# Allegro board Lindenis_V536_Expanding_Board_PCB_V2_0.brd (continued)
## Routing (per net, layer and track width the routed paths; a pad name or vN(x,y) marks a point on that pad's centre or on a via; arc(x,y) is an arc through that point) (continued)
SDC0-CLK: length 26.1
  TOP w0.102: v1(91.69,15.62) 90.97,14.9 77.05,14.9 74.17,17.78 73.08,17.78 72.77,18.08 U901.100
  BOTTOM w0.102: J3.5 89.15,14.34 89.53,14.73 90.17,14.73 91.65,16.21 D11.1 v1(91.69,15.62)
SDC0-CMD: length 19.8
  TOP w0.102: v1(88.14,15.62) 87.72,15.2 77.25,15.2 74.04,18.41 U901.101
  BOTTOM w0.102: J3.3 86.94,15.02 D12.1 v1(88.14,15.62)
SDC0-D0: length 27.5
  TOP w0.102: U901.99 71.5,18.16 71.75,17.91 72.47,17.91 72.9,17.48 74.04,17.48 76.92,14.59 91.56,14.59 v1(92.58,15.62)
  BOTTOM w0.102: v1(92.58,15.62) D15.1 92.2,15.83 92.2,15.37 91.35,14.51 J3.7
SDC0-D1: length 29.8
  TOP w0.102: v1(93.47,15.62) 92.24,14.39 76.79,14.39 73.91,17.27 72.81,17.27 72.43,17.65 70.61,17.65 70.23,18.03 U901.98
  BOTTOM w0.102: J3.8 92.45,14.09 93.03,14.67 93.03,15.77 D16.1 v1(93.47,15.62)
SDC0-D2: length 14.1
  TOP w0.102: v1(84.71,15.88) 77.85,15.88 76.58,17.14 U901.103
  BOTTOM w0.102: J3.1 84.75,14.26 85.34,14.86 D14.1 85.05,16.21 v1(84.71,15.88)
SDC0-D3: length 18
  TOP w0.102: U901.102 75.31,17.78 77.57,15.52 84.86,15.52 85.02,15.69 v1(86.74,15.69)
  BOTTOM w0.102: v1(86.74,15.69) 87.25,16.19 RC9.1 D13.1 85.84,15.57 J3.2
SDC0-DET: length 19.6
  TOP w0.102: v1(93.85,17.65) 92.71,16.51 78.16,16.51 77.85,16.81 U901.104
  BOTTOM w0.102: v1(93.85,17.65) 94.36,17.14 R401.2
TS: length 62.2
  TOP w0.102: U901.29 58.8,69.85 v1(58.67,69.98) ; v1(44.58,71.58) 43.99,71.58 42.29,73.28 v1(40.13,73.28)
  BOTTOM w0.102: v1(44.58,71.58) 44.7,71.7 44.7,73.18 44.81,73.28 48.64,73.28 50.24,71.68 54.18,71.68 54.48,71.37 54.48,69.98 54.74,69.72 58.42,69.72 v1(58.67,69.98) ; v1(40.13,73.28) 40,73.41 27.05,73.41 26.21,72.57 20.78,72.57 18.03,75.31 12.45,75.31 9.78,72.64 7.11,72.64 5.84,73.91 J1.2
TWI1-SCK: length 108.4
  TOP w0.102: v1(51.69,81.41) 53.34,79.76 78.52,79.76 78.82,80.06 80.6,80.06 v1(80.84,79.82) ; v1(123.83,65.41) 123.74,65.41 R531.1 122.83,64.49 121.64,64.49 120.65,63.5 120.65,60.58 119.53,59.46 111.91,59.46 110.49,58.04 98.78,58.04 97.03,59.79 97.03,70.23 96.65,70.61 84.63,70.61 v1(84.25,70.23) 88.39,70.23 89.28,69.34 U901.5 ; JL6.6 124.95,65.64 v1(124.84,65.53)
  BOTTOM w0.102: R41.2 80.69,79.97 v1(80.84,79.82) 80.84,79.81 80.14,79.11 80.14,77.72 U11.2 81.28,76.58 81.28,74.58 83.72,72.14 83.72,70.76 v1(84.25,70.23) ; v1(124.84,65.53) 123.95,65.53 v1(123.83,65.41) ; R75.1 52.32,80.77 v1(51.69,81.41) 51.69,82.04 J36.3
TWI1-SDA: length 109.8
  TOP w0.102: v1(79.71,79.71) 79.71,79.71 79.48,79.48 53.12,79.48 51.19,81.41 v1(50.8,81.41) ; JL6.5 124.6,65.14 123.95,65.79 R532.1 122.83,65.38 121.64,65.38 120.45,64.19 120.45,60.66 119.45,59.66 111.83,59.66 110.41,58.24 98.86,58.24 97.28,59.82 97.28,70.26 96.73,70.82 84.1,70.82 83.82,70.54 v1(83.82,69.95) 83.9,69.88 84.4,69.88 84.55,70.03 87.71,70.03 88.01,69.72 U901.6
  BOTTOM w0.102: R40.2 79.55,79.97 79.71,79.8 v1(79.71,79.71) 79.71,78.69 79.25,78.23 79.25,76.07 U11.1 81.15,74.17 81.41,74.17 83.52,72.06 83.52,70.26 v1(83.82,69.95) ; J36.4 50.8,81.66 v1(50.8,81.41) 51.43,80.77 R76.1
TXC: length 54.3
  TOP w0.102: v1(28.5,59.74) 28.42,59.82 27.97,59.82 26.8,60.98 UM1.20
  BOTTOM w0.102: v1(28.5,59.74) 28.55,59.79 28.55,60.73 30.94,63.12 38.48,63.12 40.51,65.15 42.85,65.15 43.61,65.91 71.75,65.91 74.04,68.2 74.04,68.88 CM11.1 RM12.1
TXCTL: length 42.7
  TOP w0.102: UM1.19 v1(26.4,60.45)
  BOTTOM w0.102: v1(26.4,60.45) 26.4,61.07 30.28,64.95 37.57,64.95 39.51,66.89 42.18,66.89 43.33,68.05 64.28,68.05 RM54.1
TXD0: length 48.1
  TOP w0.102: UM1.18 26,60.08 v1(26.42,59.67)
  BOTTOM w0.102: v1(26.42,59.67) 26.74,59.67 27,59.93 27,61.09 30.42,64.52 37.72,64.52 39.67,66.47 42.33,66.47 43.45,67.59 68.48,67.59 68.82,67.93 RM5.8
TXD1: length 49.9
  TOP w0.102: v1(25.65,59.67) 25.6,59.72 UM1.17
  BOTTOM w0.102: RM5.7 69.47,67.57 69.27,67.36 43.51,67.36 42.42,66.27 39.76,66.27 37.8,64.31 30.51,64.31 27.2,61.01 27.2,59.84 26.67,59.31 26.01,59.31 v1(25.65,59.67)
TXD2: length 51.1
  TOP w0.102: v1(25.15,59.67) 25.2,59.73 UM1.16
  BOTTOM w0.102: v1(25.15,59.67) 25.71,59.11 26.75,59.11 27.41,59.76 27.41,60.93 30.59,64.11 37.89,64.11 39.84,66.07 42.5,66.07 43.57,67.13 69.55,67.13 69.97,67.56 RM5.6
TXD3: length 52.4
  TOP w0.102: UM1.15 24.8,59.83 24.79,59.82 24.79,59.52 25.14,59.17 v1(25.14,59.16)
  BOTTOM w0.102: RM5.5 70.62,67.45 70.08,66.9 43.63,66.9 42.59,65.86 39.93,65.86 37.97,63.91 30.68,63.91 27.61,60.84 27.61,59.67 26.84,58.9 25.43,58.9 25.17,59.16 v1(25.14,59.16)
UART4_RX: length 24
  TOP w0.102: v1(96.09,69.62) 95.4,70.31 91.26,70.31 90.55,69.6 U901.4 ; Q2.2 103.06,73.68 R13.1 103.5,72.18 103.5,68.71 103.21,68.41 RG1.1 RG4.1 103.59,67.35 v1(103.63,67.31)
  BOTTOM w0.102: v1(96.09,69.62) 99.92,69.62 102.23,67.31 v1(103.63,67.31)
UART4_TX: length 21
  TOP w0.102: v1(95.58,69.62) 95.17,70.03 92.13,70.03 91.82,69.72 U901.3 ; R348.2 99.69,74.93 101.09,73.53 101.09,72.64 101.68,72.06 101.68,68.76 102.02,68.41 RG2.1 RG5.1 v1(101.52,67.35)
  BOTTOM w0.102: v1(95.58,69.62) 95.59,69.62 95.99,69.22 99.66,69.22 v1(101.52,67.35)
USB1-DM: length 16.9
  TOP w0.114: U51.4 33.42,47.12 33.51,47.22 33.89,47.22 43.79,57.12 44.31,57.12 44.42,57.01 44.42,56.76 44.54,56.64 U901.49
USB1-DP: length 16.9
  TOP w0.114: U901.48 44.54,57.91 44.42,57.8 44.42,57.54 44.31,57.43 43.66,57.43 33.76,47.53 33.51,47.53 33.42,47.62 U51.3
USB1_DM: length 11.2
  TOP w0.114: U32.25 36.42,42.11 36.25,42.29 35.77,42.29 35.33,42.72 35.33,44.5 35.92,45.09 38.18,45.09 38.84,45.74 38.84,47.14 38.26,47.72 37.71,47.72 37.62,47.62 U51.8
USB1_DP: length 11.2
  TOP w0.114: U32.26 36.42,42.76 36.25,42.59 35.89,42.59 35.64,42.85 35.64,44.37 36.04,44.78 38.3,44.78 39.14,45.62 39.14,47.27 38.38,48.03 37.71,48.03 37.62,48.13 U51.9
USB-SEL: length 2.3
  TOP w0.102: R419.1 31.91,48.13 U51.2
USB_RESET: length 4.7
  TOP w0.102: C218.2 R229.1 R238.2 28.31,36.26 U32.13
USBVBUS: length 98.8
  TOP w0.406: v1(92.7,47.24) 92.46,47.24 v1(86.87,52.83) ; v1(51.41,59.82) 51.41,52.93 v1(50.8,52.32)
  TOP w0.508: 9.56,40.71 J9.8 ; J9.8 10.44,39.83 ; J9.8 11.32,40.71 ; J9.4 14.03,40.71 ; J9.4 13.15,41.59 ; J9.4 12.27,40.71 ; J9.4 13.15,39.83
  BOTTOM w0.406: v2(19.43,43.18) 27.18,50.93 38.61,50.93 47.5,59.82 v1(51.41,59.82) ; v1(50.8,52.32) 50.83,52.3 86.33,52.3 v1(86.87,52.83) ; U27.11 v1(92.7,47.24)
  vias: v2(19.43,42.42) v2(19.56,29.21) v2(20.32,29.21)
USIM_CLK: length 61.9
  BOTTOM w0.102: RL25.1 CL29.1 111.3,17.23 110.49,18.03 108.46,18.03 105.79,20.7 105.79,27.69 104.01,29.46 92.52,29.46 87.12,34.86 87.12,51.05 91.3,55.24 U27.19
USIM_DATA: length 65.1
  TOP w0.102: v1(105.41,25.91) v1(106.81,25.91)
  BOTTOM w0.102: U27.17 90.07,53.24 87.88,51.05 87.88,35.18 92.84,30.23 104.65,30.23 106.81,28.07 v1(106.81,25.91) ; RL40.2 112.18,15.11 CW30.1 110.89,15.6 109.88,15.6 109.75,15.73 107.46,15.73 106.81,16.38 106.81,19.3 105.59,20.52 105.59,25.73 v1(105.41,25.91)
USIM_RST: length 57.8
  BOTTOM w0.102: RL24.1 CL28.1 111.3,20.91 110.36,21.84 107.06,21.84 106.3,22.61 106.3,27.94 104.27,29.97 92.73,29.97 87.63,35.07 87.63,51.18 90.69,54.24 U27.18
USIM_VDD: length 78.4
  TOP w0.254: v1(112.35,25.06) v1(104.48,25.06)
  TOP w0.406: v1(104.9,20.19) 107.44,20.19 v1(107.57,20.07)
  BOTTOM w0.254: RL41.1 v1(112.35,25.06)
  BOTTOM w0.305: TP83.1 109.09,18.41 112.58,18.41 112.86,18.69 112.86,18.7 CL31.1
  BOTTOM w0.406: v1(107.57,20.07) 108.71,18.92 TP83.1 ; v1(104.9,20.19) 104.9,24.64 v1(104.48,25.06) 104.48,27.61 103.26,28.83 92.26,28.83 86.49,34.6 86.49,51.18 91.54,56.24 U27.20 ; JL26.C6 113.84,18.41 CL31.1 CL32.1
V-BAT:
  vias: v2(116.84,26.29) v2(117.6,26.29) v2(118.36,26.29) v2(119.13,26.29)
VLED+: length 25.5
  TOP w0.305: J7.35 122.93,50.56 v2(122.68,50.8) 122.94,51.06 J7.36 125.29,51.06 v1(125.95,50.39)
  TOP w0.508: v2(117.22,54.99) 117.28,54.94 D41.2 ; v2(111.44,56.71) C295.2 111.44,54.63 C293.2 U39.5
  BOTTOM w0.305: TP67.1 v1(125.95,50.39)
  BOTTOM w0.508: v2(111.44,56.71) 115.5,56.71 v2(117.22,54.99) 121.41,50.8 v2(122.68,50.8)
VLED-: length 17.3
  TOP w0.305: J7.28 123.08,47.06 v2(122.58,47.56) J7.29 125.66,47.56 v1(125.86,47.75)
  BOTTOM w0.305: v1(125.86,47.75) 126.49,47.12 TP64.1
  BOTTOM w0.508: v2(115.06,55.88) 122.58,48.36 v2(122.58,47.56)
WL-PMU-EN: length 93
  TOP w0.102: v1(87.6,60.91) 87.82,61.13 v1(87.82,66.45) 87.92,66.55 93.73,66.55 94.74,65.53 U901.154
  BOTTOM w0.102: v1(87.82,66.45) 87.63,66.64 R527.2 ; U12.9 34.67,30 34.67,31.62 37.26,34.21 37.26,44.03 49.01,55.78 78.64,55.78 80.01,57.15 82.26,57.15 85.87,60.76 87.45,60.76 v1(87.6,60.91)
WL-SDIO-CLK: length 90.8
  TOP w0.102: v1(93.09,63.55) 92.96,63.42 92.96,61.98 94.49,60.45 U901.150
  BOTTOM w0.102: v1(93.09,63.55) 93.07,63.58 85.55,63.58 81.55,59.58 78.51,59.58 77.24,58.32 48.15,58.32 34.66,44.83 34.66,35.37 31.67,32.38 29.34,32.38 28.58,31.62 28.58,30.1 27.64,29.16 U12.3
WL-SDIO-CMD: length 84.4
  TOP w0.102: v1(93.85,62.48) 94.61,61.72 U901.151
  BOTTOM w0.102: U12.7 32.64,29.96 32.64,31.58 35.69,34.63 35.69,44.33 48.56,57.2 78.03,57.2 79.27,58.45 82.07,58.45 86.06,62.43 93.8,62.43 v1(93.85,62.48)
WL-SDIO-D0: length 93.1
  TOP w0.102: U901.149 94.49,59.18 92.35,61.32 v1(92.35,64.39)
  BOTTOM w0.102: U12.2 28.08,33.4 31.39,33.4 33.69,35.7 33.69,45.13 47.79,59.23 76.98,59.23 78.27,60.53 81.39,60.53 85.45,64.59 91.59,64.59 91.69,64.69 92.05,64.69 v1(92.35,64.39)
WL-SDIO-D1: length 92.3
  TOP w0.102: U901.148 94.36,57.91 91.85,60.43 91.85,64.33 v1(91.84,64.34)
  BOTTOM w0.102: U12.4 27.64,31.58 29.21,33.15 31.5,33.15 33.94,35.6 33.94,45.09 47.88,59.03 77.06,59.03 78.36,60.33 81.47,60.33 85.49,64.34 v1(91.84,64.34)
WL-SDIO-D2: length 85.2
  TOP w0.102: U901.153 94.36,64.26 v1(93.85,63.75)
  BOTTOM w0.102: v1(93.85,63.75) 93.85,63.49 93.2,62.84 85.89,62.84 81.9,58.85 79.1,58.85 77.86,57.61 48.3,57.61 35.27,44.57 35.27,44.41 35.27,34.88 32.18,31.79 30.47,31.79 U12.6
WL-SDIO-D3: length 82.5
  TOP w0.102: U901.152 v1(93.85,62.99)
  BOTTOM w0.102: v1(93.85,62.99) 93.5,62.64 85.97,62.64 81.99,58.65 79.19,58.65 77.94,57.4 48.38,57.4 35.47,44.49 35.47,34.79 U12.8
WL-WAKE-AP: length 127
  TOP w0.102: v1(89.15,60.58) 89.15,60.27 84.94,56.05 84.94,53.04 89.66,48.32 89.66,43.43 89.56,43.33 89.56,43.03 89.66,42.93 89.66,23.82 86.67,20.83 80.77,20.83 80.39,20.45 U901.106
  BOTTOM w0.102: U12.11 36.45,29.77 36.45,33.11 37.46,34.13 37.46,43.94 49.1,55.58 78.72,55.58 80.09,56.95 82.35,56.95 85.95,60.55 89.13,60.55 v1(89.15,60.58)
X1: length 8.1
  TOP w0.102: U32.6 29.29,40.81 27.56,42.55 27.56,42.88 C338.1 26.97,43.05 24.86,43.05 Y3.1
X32KFOUT: length 83.7
  TOP w0.102: v1(91.19,61.72) 91.19,59.82 94.36,56.64 U901.147
  BOTTOM w0.102: v1(91.19,61.72) 91.18,61.72 86.1,61.72 82.12,57.73 79.71,57.73 78.46,56.49 48.61,56.49 36.45,44.34 36.45,34.55 33.64,31.73 U12.10
XI2: length 5.6
  TOP w0.102: Y3.3 26.38,42.21 C230.2 29.22,40.16 U32.7
XTAL-IN: length 7.5
  TOP w0.102: X3.1 25.02,71.5 25.02,69.75 C139.2 24.89,68.95 24.89,68.11 24.8,68.02 UM1.36
XTAL-OUT: length 47.3
  TOP w0.102: R51.2 24.16,67.82 v1(24.38,67.82) 24.51,67.69 24.51,66.41 24.4,66.3 UM1.37
  BOTTOM w0.102: RM56.1 65.15,72.06 64.69,72.52 62.86,72.52 62.48,72.14 62.48,71.25 60.2,68.96 42.95,68.96 41.66,67.67 27.41,67.67 27.05,67.31 24.89,67.31 v1(24.38,67.82)
N17770502: length 1.9
  BOTTOM w0.381: RL23.2 127.51,64.21 CW27.1 127.51,63.16 RL20.1
N17770537: length 6.6
  BOTTOM w0.381: U27.82 126.42,57.24 arc(127.17,57.55) 127.49,58.31 CW26.1 127.49,61.41 RL20.2
N17770634: length 7.6
  BOTTOM w0.381: RL23.1 127.51,71.12 arc(127.42,71.59) 127.15,71.98 v1(126.75,72.39)
N17772040: length 10.2
  BOTTOM w0.102: JL26.C7 115.19,15.88 114.53,16.53 113.01,16.53 112.49,16 DL51.2 112.35,15.96 RL40.1 112.69,14.61 109.09,14.61 TP84.1
N17772586: length 8
  BOTTOM w0.102: TP79.1 111,23.11 111.89,22.23 112.69,22.23 RL41.2 113.71,22.23 JL26.C1
N17773525: length 3.1
  TOP w0.254: UL9.4 103,39.16 CL94.1 RL38.1
N17773548: length 4.4
  TOP w0.254: RL84.2 CL64.2 102.7,41.32 103.09,40.92 UL9.3 103.84,40.94 RL39.2
N17773558: length 17.6
  TOP w0.254: CL64.1 RL84.1 100.63,40.47 100.33,40.77 100.33,42.04 101.22,42.93 107.06,42.93 110.85,39.14 LP7.2
N17773576: length 5.9
  TOP w0.254: CL88.2 106.6,40.85 107.57,39.88 107.57,37.36 LP7.1
N17773604: length 1.5
  TOP w0.254: UL9.1 105.72,42.4 CL88.1
N17784951: length 2.5
  BOTTOM w0.102: QL13.1 89.09,42.06 RL70.1 RL69.1
N17956748: length 9.6
  BOTTOM w0.102: 115.95,19.68 115.23,19.68 DL49.2 RL24.2 113.2,20.74 112.88,20.43 110.72,20.43 110.36,20.07 109.35,20.07 TP80.1
N17956763: length 8.8
  BOTTOM w0.102: TP81.1 109.07,16.53 112.58,16.53 113.07,17.02 RL25.2 DL50.2 113.96,17.14 JL26.C3
N19642444: length 4.5
  BOTTOM w0.508: RC1.2 C275.2 89.28,15.85 88.05,14.61 J3.4
N19809825: length 2.9
  BOTTOM w0.102: J3.9 93.54,13.79 94.36,14.6 R401.1
N19810892: length 3
  BOTTOM w0.254: R20.1 43.43,10.58 R19.1 44.24,11.56 C56.2
N19810945: length 2.8
  BOTTOM w0.254: C56.1 46.05,9.75 R24.1 R23.1
N19811956: length 14
  TOP w0.254: J21.2 66.17,7.03 66.17,9.78 67.56,11.18 68.96,11.18 70.23,12.45 70.23,12.94 70.88,13.59 D39.2 71.04,13.46 v1(71.04,12.24)
  BOTTOM w0.254: R422.2 v1(71.04,12.24)
N19811968: length 7.5
  TOP w0.254: 64.39,9.77 64.39,10.08 D40.2 67.9,12.24 v1(68.03,12.11)
  BOTTOM w0.254: R33.2 v1(68.03,12.11)
N19812150: length 2.4
  BOTTOM w0.254: R422.1 R423.1 70.19,14.99 C384.2
N19812152: length 2.4
  BOTTOM w0.254: C75.2 68.88,15.12 R421.1 R33.1
N19829872: length 6.2
  TOP w0.102: KK1.4 93.58,9.4 RK2.1 RK3.2
N19829876: length 12.4
  TOP w0.102: RK4.2 101.05,8.51 RK3.1 99.1,6.19 96.09,3.17 94.85,3.17 KK2.4
N19829887: length 8.6
  TOP w0.102: RK5.2 RK4.1 102.02,4.91 103.65,3.28 KK3.4
N19829903: length 27.1
  TOP w0.102: v1(100.46,8.86) 100.56,8.86 101.09,9.4 RK5.1 ; v1(97.54,8.89) 96.65,8 84.33,8 83.4,8.93 KK4.4 81.57,8.93 80.65,8 v1(76.2,8)
  BOTTOM w0.102: v1(97.54,8.89) 97.56,8.86 v1(100.46,8.86) ; RK6.2 76.16,8.04 v1(76.2,8)
N19829909: length 10.1
  TOP w0.102: KK5.4 82.69,2.14 77.64,7.2 v1(76.16,7.2)
  BOTTOM w0.102: RK6.1 v1(76.16,7.2)
N19829940: length 2.8
  TOP w0.102: RP62.1 122.13,27.52 121.5,26.89 KP1.4
N19829965: length 3.3
  TOP w0.102: RK7.1 120.44,18.08 120.89,18.53 KK6.4
N19833462: length 2.7
  TOP w0.254: RH16.1 110.74,17.32 110.74,17.6 DH12.2
N19840129: length 1.3
  BOTTOM w0.508: QL5.3 19.94,8.85 RL49.1
N19841860: length 2.8
  BOTTOM w0.254: U2.4 38.19,69.43 R45.1 R46.2
N19841911: length 1.5
  BOTTOM w0.508: D7.1 42.37,76.04 R39.2
N19843250: length 3.8
  TOP w0.381: RG6.1 120.4,76.12 CG2.2 120.41,74.65 arc(120.16,74.04) 119.55,73.79 RG3.2
N19843374: length 2.9
  TOP w0.102: RG4.2 103,66.14 103.86,65.28 U8.20
N19843376: length 4
  TOP w0.102: U8.21 104.43,64.18 RG5.2
N19843437: length 3
  TOP w0.381: ANT3.3 120.41,80.87 CG3.2 120.41,77.91 RG6.2
N19850791: length 7
  TOP w0.102: R239.2 28.32,45.89 28.32,43.31 29.51,42.11 U32.4
N19866924: length 1.3
  TOP w0.102: RL1.2 14.15,16.01 DL6.2
N19866926: length 3.6
  TOP w0.102: QL1.3 17.86,13.63 RL56.1 RL4.2
N19866930: length 3.6
  TOP w0.102: QL3.3 13.16,13.76 RL13.1 RL1.1
N19866943: length 4.2
  TOP w0.102: QL1.1 19.16,11.62 RL85.1 20.62,13.08 RL6.1
N19866974: length 4.5
  TOP w0.102: QL3.1 14.84,11.75 RL15.1 15.92,12.83 RL14.1
N19867123: length 1.4
  TOP w0.102: RL4.1 18.71,16.76 DL7.2
N19875396: length 2.7
  TOP w0.508: R316.2 R318.1 116.2,55.35 U39.3
N19875466: length 1.8
  TOP w0.508: R319.2 C292.2 R316.1
N19875497: length 5.4
  TOP w0.305: D41.1 116.07,53.15 U39.1 115.9,51.15 L12.2
N19896949: length 6
  TOP w0.102: DM1.1 34.25,71.27 RM34.2 32.79,71.42 30.5,71.42 29.33,70.25 RM28.1
N19896956: length 5.8
  TOP w0.102: DM1.2 33.99,70.22 RM35.1 32.94,70.28 32,71.22 30.58,71.22 30.05,70.69 RM33.1
N19897306: length 7.4
  TOP w0.406: CM19.1 33.5,66.89 LM1.2
  TOP w0.508: RM42.1 33.12,65.84 LM1.2 ; CM19.1 34.85,66.58 CM18.2 36.39,67.33 RM44.2 37.86,67.33 RM43.2
N19897342: length 2.6
  TOP w0.102: R51.1 24.43,69.28 C140.2 24.3,70.09 X3.3
N19898869: length 6.2
  TOP w0.102: U19.1 16.8,67.19 C206.1
N19898879: length 16
  BOTTOM w0.102: RM55.2 1.75,70.66 1.75,64.87 3.54,63.08 U19.13
N19898907: length 6.7
  BOTTOM w0.102: RM2.2 1.98,70 1.98,66.8 U19.12
N19916216: length 6.9
  TOP w0.102: R348.1 99.69,79.8 J12.5
N19916242: length 6.4
  TOP w0.102: J12.4 102.11,79.71 Q2.3
N19933444: length 48.7
  TOP w0.102: v1(25.53,50.16) 27.43,50.16 29.59,48.01 R420.1 R419.2 R292.2 ; J80.2 5.5,28.19 v1(15.88,28.19)
  BOTTOM w0.102: v1(25.53,50.16) 25.53,49.78 19.94,44.2 19.43,44.2 18.67,43.43 18.67,32.38 18.16,31.88 18.16,30.48 v1(15.88,28.19)
N19963769: length 2.6
  BOTTOM w0.254: U23.4 57.58,14.72 C189.1
N19963781: length 3.6
  BOTTOM w0.254: R177.2 65.83,11.6 R179.1 64.2,13.22 U23.10
N19963785: length 1.3
  BOTTOM w0.254: C470.2 R177.1
N19963787: length 3.4
  BOTTOM w0.254: R179.2 64.98,13.3 R181.2 64.59,13.72 U23.9
N19963809: length 3.2
  BOTTOM w0.254: U23.8 R184.2 64.98,14.26 R183.2
N19963840: length 3.5
  BOTTOM w0.254: R174.1 56.18,12.53 R178.1 56.83,13.22 U23.1
N19963846: length 3.4
  BOTTOM w0.254: R178.2 56.18,13.42 R180.1 56.44,13.72 U23.2
N19963852: length 1.5
  BOTTOM w0.254: R174.2 56.3,11.56 C183.1
N19963856: length 2.9
  BOTTOM w0.254: R185.1 R182.1 56.3,14.22 U23.3
N19963865: length 2.6
  BOTTOM w0.254: U23.6 62.42,15.22 C468.2
N19963871: length 2.6
  BOTTOM w0.254: U23.5 58.74,15.22 C468.1
N19965778: length 1.5
  TOP w0.102: RU14.1 20.63,33.16 UU3.3
N19978083: length 4.2
  TOP w0.508: J81.1 10.16,9.82 ; J81.1 8.98,8.89 ; J81.1 10.16,7.96 ; J81.1 11.34,8.89
N19984458: length 4.3
  TOP w0.102: R550.2 R549.1 6.32,14.34 USB1.4
N22541145: length 6.3
  TOP w0.102: RH5.2 DH2.1 108.16,12.45 109.47,12.45 109.93,11.99 JH1.19
N198287081: length 3.4
  TOP w0.406: R192.2 103.63,16.54 103.23,16.94 102.03,16.94 101.63,16.54 U902.11
N198400281: length 1.4
  BOTTOM w0.102: RL48.2 19.51,12.17 QL5.1
N198419350: length 1.5
  BOTTOM w0.254: R43.1 42.02,69.92 U2.3
N199505671: length 1.7
  TOP w0.254: R269.1 114.13,45.73 U24.3

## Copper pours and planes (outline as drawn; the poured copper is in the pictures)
AVDD10 on BOTTOM: 21.84,62.1 22.1,61.85 22.73,61.85 22.99,62.1 22.99,63.75 21.72,65.02 21.72,66.29 22.35,66.93 23.24,66.93 23.62,66.55 23.62,65.66 23.88,65.41 24.13,65.41 24.38,65.66 24.38,66.93 23.49,67.82 21.97,67.82 21.08,66.93 21.08,64.26 21.84,63.5
GND on BOTTOM: 3.81,0.25 1.3,1.3 0.25,3.81 0.25,81.2 1.3,83.71 3.81,84.75 126.27,84.75 128.78,83.71 129.82,81.2 129.82,3.81 128.78,1.3 126.27,0.25 ; 29 cut-outs
GND on L2GND: 3.81,0.26 1.3,1.3 0.26,3.81 0.26,81.2 1.3,83.71 3.81,84.75 126.27,84.75 128.78,83.71 129.82,81.2 129.82,3.81 128.78,1.3 126.27,0.26
GND on L3SIG: 3.81,0.25 1.3,1.3 0.25,3.81 0.25,81.2 1.3,83.71 3.81,84.75 126.27,84.75 128.78,83.71 129.82,81.2 129.82,3.81 128.78,1.3 126.27,0.25
GND_SIGNAL on TOP: 104.65,74.42 105.92,74.42 106.05,74.3 106.05,61.47 105.92,61.34 104.65,61.34 104.52,61.21 104.52,60.2 104.65,60.07 109.22,60.07 110.24,61.09 115.82,61.09 116.08,61.34 116.08,71.5 116.71,72.14 120.02,72.14 122.81,74.93 122.81,83.44 122.55,83.69 118.36,83.69 117.73,83.06 117.73,76.33 117.47,76.07 104.77,76.07 104.52,75.82 104.52,74.55
GND_SIGNAL on L2GND: 117.22,70.74 118.62,70.74 121.67,73.79 121.67,79.12 122.81,80.26 122.81,83.31 122.3,83.82 118.49,83.82 117.73,83.06 117.73,76.71 117.22,76.2 104.9,76.2 104.52,75.82 104.52,61.98 105.41,61.09 115.19,61.09 116.2,62.1 116.2,69.72
GND_SIGNAL on L3SIG: 121.67,73.79 121.67,79.12 122.81,80.26 122.81,83.31 122.3,83.82 118.49,83.82 117.73,83.06 117.73,76.71 117.22,76.2 104.9,76.2 104.52,75.82 104.52,66.55 109.86,61.21 115.44,61.21 116.2,61.98 116.2,69.6 117.35,70.74 118.62,70.74
VBAT on TOP: 55.88,71.37 55.88,68.33 56.01,68.2 56.64,68.2 56.64,69.85 56.77,69.98 57.02,69.98 57.15,69.85 57.15,68.2 57.78,68.2 57.91,68.33 57.91,71.37 57.78,71.5 56.01,71.5
VBAT on BOTTOM: 6.73,76.71 6.73,73.66 7.24,73.15 9.65,73.15 12.38,75.88 12.38,77.41 16.76,81.79 30.48,81.79 30.99,81.28 30.99,80.26 31.62,79.63 35.69,79.63 36.2,80.14 36.2,81.28 36.7,81.79 41.4,81.79 42.62,80.57 42.62,78.49 46.75,74.36 48.83,74.36 50.67,72.52 54.61,72.52 55.5,71.63 55.5,70.26 55.78,69.98 57.53,69.98 57.78,70.23 57.78,72.52 56.13,74.17 52.58,74.17 47.88,78.87 45.72,78.87 45.29,79.3 45.29,81.58 42.67,84.2 15.37,84.2 9.65,78.49 9.65,77.47 9.14,76.96 6.99,76.96
VCC-1V8 on TOP: 115.7,48.9 119.63,48.9 122.68,45.85 122.68,43.31 122.94,43.05 122.94,42.04 122.68,41.78 122.07,41.78 120.14,43.71 120.14,46.86 119.25,47.75 115.7,47.75 115.32,48.13 115.32,48.51
VCC-3V3 on TOP: 97.92,79.38 97.92,75.95 100.84,73.03 100.84,62.23 101.09,61.98 101.98,61.98 102.11,61.85 102.11,60.33 101.73,59.94 99.95,59.94 99.69,60.2 99.69,72.52 96.14,76.07 94.74,76.07 94.36,76.45 94.36,78.74 92.96,80.14 81.28,80.14 80.52,80.9 80.52,81.41 80.77,81.66 95.63,81.66
VCC-3V3 on TOP: 53.59,83.31 53.59,81.79 54.61,80.77 78.61,80.77 78.87,81.03 78.87,81.28 78.49,81.66 56.39,81.66 56.13,81.92 56.13,83.44 55.63,83.95 54.23,83.95
VCC-3V3 on TOP: 35.94,77.6 36.2,77.85 36.2,78.94 36.7,79.45 36.7,81.53 37.34,82.17 47.24,82.17 47.37,82.3 47.37,83.82 46.99,84.2 32.26,84.2 30.86,82.8 30.86,77.85 31.12,77.6
VCC-3V3 on TOP: 23.37,34.67 23.62,34.42 26.92,34.42 27.18,34.67 27.18,35.81 26.92,36.07 26.42,36.07 26.16,36.32 23.62,36.32 23.37,36.07
VCC-3V3 on TOP: 114.17,48.39 113.79,48.01 110.36,48.01 109.16,49.21 104.97,49.21 99.57,54.61 99.57,55.37 99.95,55.75 103.12,55.75 108.2,50.67 109.98,50.67 111.38,49.28 114.05,49.28 114.17,49.15
VCC-3V3 on TOP: 44.58,55.75 44.58,54.99 46.1,54.99 46.23,54.86 46.23,54.61 46.1,54.48 44.58,54.48 44.58,53.72 46.74,53.72 48.39,55.37 49.53,55.37 50.04,55.88 50.04,59.31 49.4,59.94 49.4,60.58 49.78,60.96 55.63,60.96 57.15,59.44 78.11,59.44 82.04,63.37 82.04,64.52 81.66,64.9 79.38,64.9 76.58,62.1 58.93,62.1 57.28,63.75 48.77,63.75 46.23,61.21 46.23,56.01 45.97,55.75
VCC-3V3 on BOTTOM: 97.54,79.63 97.28,79.88 94.61,79.88 94.23,79.5 94.23,76.83 94.74,76.33 97.03,76.33 97.54,76.83
VCC-3V3 on BOTTOM: 49.66,79.25 53.59,79.25 53.85,79.5 53.85,80.01 54.1,80.26 54.86,80.26 56.26,81.66 56.26,83.44 55.63,84.07 53.98,84.07 53.47,83.57 53.47,81.66 52.83,81.03 52.83,80.39 52.7,80.26 51.05,80.26 50.93,80.39 50.93,80.77 50.55,81.15 49.91,81.15 47.5,83.57 46.35,83.57 46.23,83.44 46.23,82.68
VCC-3V3 on BOTTOM: 78.03,81.66 81.41,81.66 81.79,81.28 81.79,80.9 81.53,80.64 77.98,80.64 77.77,80.85 77.77,81.41
VCC-3V3 on BOTTOM: 31.5,20.57 30.61,21.46 26.16,21.46 21.95,25.68 21.95,34.52 23.75,36.32 25.27,36.32 26.16,35.43 26.16,33.02 24.33,31.19 24.33,27.56 27.64,24.26 34.8,24.26 36.58,26.04 36.58,29.34 36.7,29.46 36.7,31.75 37.34,32.38 39.24,32.38 39.75,31.88 39.75,25.91 33.78,19.94 33.78,13.34 34.29,12.83 37.72,12.83 37.97,13.08 37.97,14.99 38.48,15.49 40.77,15.49 41.4,14.86 42.29,14.86 51.43,24 83.69,24 85.6,22.1 92.33,22.1 96.77,17.65 103,17.65 104.52,19.18 105.03,19.18 105.54,18.67 105.54,14.99 105.28,14.73 104.39,14.73 103.63,15.49 96.9,15.49 93.09,19.3 82.42,19.3 80.52,21.21 61.34,21.21 60.58,20.45 60.58,17.91 60.2,17.53 56.13,17.53 55.75,17.91 55.75,20.57 54.86,21.46 52.45,21.46 42.93,11.94 39.37,11.94 38.61,11.18 32.64,11.18 31.5,12.32
VCC-3V3 on L3SIG: 22.35,35.31 22.86,34.8 26.16,34.8 28.45,37.08 28.45,45.72 34.1,51.37 37.66,51.37 45.59,59.31 47.12,59.31 48.39,60.58 48.39,61.72 47.88,62.23 44.2,62.23 40.26,58.29 27.18,58.29 22.35,53.47
VCC-3V3 on L3SIG: 99.44,60.45 99.44,55.12 99.82,54.74 101.35,54.74 101.85,55.24 101.85,60.2 101.35,60.71 99.69,60.71
VCC-3V3 on L3SIG: 80.64,62.23 87.1,62.23 88.34,63.47 88.75,63.47 93.85,68.58 93.85,73.03 97.66,76.83 97.66,78.74 96.77,79.63 91.69,79.63 84.84,72.77 84.84,68.33 80.26,63.75 80.26,62.61
VCC-5V on TOP: 104.39,37.59 104.01,37.21 102.87,37.21 102.49,36.83 102.49,26.29 102.74,26.04 103.63,26.04 104.77,27.18 104.77,34.54 105.28,35.05 105.28,38.86 105.16,38.99 104.52,38.99 104.39,38.86
VCC-5V on TOP: 9.53,13.08 11.81,13.08 12.57,13.84 12.57,16.13 12.19,16.51 10.54,16.51 9.53,15.49
VCC-5V on TOP: 52.07,71.25 52.07,68.33 52.2,68.2 52.7,68.2 52.83,68.33 52.83,69.85 52.96,69.98 53.21,69.98 53.34,69.85 53.34,68.33 53.47,68.2 53.98,68.2 54.1,68.33 54.1,71.25 53.85,71.5 52.32,71.5
VCC-5V on TOP: 4.06,16.13 6.35,16.13 6.99,16.76 6.99,17.4 7.24,17.65 7.75,17.65 8,17.91 8,19.56 8.76,20.32 16.54,20.32 20.09,23.88 20.83,23.88 21.34,24.38 21.34,26.8 21.08,27.05 19.43,27.05 18.92,27.56 18.92,29.97 18.67,30.23 16.76,30.23 16.59,30.05 16.59,24.89 15.32,23.62 8.13,23.62 5.33,20.83 5.33,17.53 4.32,16.51 4.19,16.51 4.06,16.38
VCC-5V on TOP: 50.8,78.74 88.65,78.74 89.15,78.23 89.15,76.71 88.65,76.2 54.86,76.2 54.48,75.82 54.48,74.8 54.23,74.55 51.94,74.55 46.35,80.14 41.53,80.14 41.02,79.63 37.21,79.63 36.96,79.88 36.96,81.53 37.46,82.04 47.5,82.04
VCC-5V on BOTTOM: 36.96,20.7 47.62,20.7 51.18,24.26 99.31,24.26 100.97,25.91 103.38,25.91 103.63,26.16 103.63,27.43 103.38,27.69 50.29,27.69 46.48,23.88 38.48,23.88 36.83,22.23 36.83,20.83
VCC-5V on BOTTOM: 87.25,80.01 87.25,77.22 87.5,76.96 89.15,76.96 89.28,77.09 89.28,78.23 90.3,79.25 90.3,79.76 89.79,80.26 87.5,80.26
VCC-5V on BOTTOM: 9.78,14.22 12.95,14.22 13.21,14.48 13.21,22.73 12.83,23.11 9.91,23.11 9.65,22.86 9.65,14.35
VCC-5V on L2GND: 51.18,70.99 51.18,60.96 52.2,59.94 55.5,59.94 56.01,60.45 56.01,70.87 55.37,71.5 51.69,71.5
VCC-5V on L3SIG: 53.98,75.95 53.72,76.2 51.94,76.2 45.97,82.17 36.7,82.17 36.32,81.79 36.32,80.01 37.08,79.25 43.94,79.25 51.31,71.88 51.31,70.48 51.94,69.85 54.23,69.85 54.61,70.23 54.61,74.04 53.98,74.68
VCC-5V on L3SIG: 56.26,61.09 57.28,60.07 57.28,55.75 56.26,54.74 51.43,54.74 50.8,54.1 47.88,54.1 37.72,43.94 37.72,33.02 39.24,31.5 39.24,21.59 38.35,20.7 26.8,20.7 20.45,14.35 9.78,14.35 9.4,14.73 9.4,22.73 10.41,23.75 12.45,23.75 23.11,34.42 26.29,34.42 28.7,36.83 28.7,45.59 34.29,51.18 37.85,51.18 45.59,58.93 46.99,58.93 49.15,61.09
ALDO1 on BOTTOM: 89.28,51.56 89.28,51.05 89.53,50.8 92.91,50.8 93.04,50.93 95.12,50.93 95.12,51.56 92.71,51.56 91.69,52.58 90.3,52.58
DC1SW on TOP: 121.54,51.94 122.94,51.94 123.06,52.07 123.06,55.5 122.17,56.39 121.16,56.39 120.78,56.01 120.78,53.72 120.9,53.59 121.28,53.59 121.41,53.47 121.41,52.07
PS on TOP: 110.62,53.34 110.62,50.67 111.63,49.66 113.54,49.66 113.79,49.91 113.79,53.21 113.54,53.47 110.74,53.47
PS on TOP: 49.53,70.74 49.53,68.33 49.66,68.2 50.16,68.2 50.29,68.33 50.29,69.85 50.42,69.98 50.67,69.98 50.8,69.85 50.8,68.33 50.93,68.2 51.43,68.2 51.56,68.33 51.56,71.37 51.94,71.75 66.04,71.75 66.93,70.87 83.57,70.87 83.82,71.12 95.89,71.12 96.27,71.5 96.27,73.41 95.38,74.3 51.94,74.3 46.86,79.38 36.96,79.38 36.45,78.87 36.45,77.47 36.83,77.09 43.18,77.09
PS on BOTTOM: 37.08,79.5 40.51,79.5 41.15,78.87 41.15,77.72 40.51,77.09 37.21,77.09 36.45,77.85 36.45,78.87
PS on L3SIG: 94.74,73.66 96.39,73.66 113.03,57.02 113.03,50.93 112.39,50.29 109.73,50.29 108.71,51.31 108.71,54.99 94.11,69.6 94.11,73.03
REGOUT on TOP: 30.61,68.07 30.61,67.44 30.23,67.06 29.34,67.06 28.07,65.79 28.07,65.53 28.32,65.28 28.7,65.28 29.84,66.42 30.61,66.42 31.24,65.79 31.24,65.28 31.5,65.02 32,65.02 32.13,65.15 32.13,65.66 31.5,66.29 31.5,68.2 30.73,68.2
USBVBUS on TOP: 14.73,39.5 16.64,41.4 19.56,41.4 19.81,41.66 19.81,43.56 19.56,43.81 16.33,43.81 14.34,41.82 9.69,41.82 9.27,41.4 9.27,39.88 9.65,39.5
USBVBUS on TOP: 19.18,27.69 19.43,27.43 20.95,27.43 21.21,27.69 21.21,29.97 20.95,30.23 19.43,30.23 19.18,29.97
USBVBUS on BOTTOM: 18.92,43.31 18.92,27.43 19.69,26.67 20.95,26.67 21.72,27.43 21.72,43.31 21.08,43.94 19.56,43.94
V-BAT on TOP: 117.35,34.42 116.97,34.42 116.71,34.16 116.71,31.62 114.55,29.46 114.55,24.38 115.06,23.88 119.38,23.88 119.89,24.38 119.89,35.94 119.38,36.45 118.75,36.45 118.49,36.2 118.49,35.56
V-BAT on BOTTOM: 116.59,32.26 116.59,27.94 115.95,27.3 115.95,26.16 116.2,25.91 119.25,25.91 119.38,26.04 119.38,26.54 119.13,26.8 119.13,27.18 118.36,27.94 118.36,32.38 118.24,32.51 116.84,32.51
VLED+ on TOP: 110.62,56.52 110.62,53.98 110.87,53.72 113.66,53.72 113.79,53.85 113.79,54.36 113.66,54.48 112.39,54.48 112.14,54.74 112.14,56.77 111.89,57.02 111.12,57.02
VLED+ on TOP: 116.84,55.37 116.84,54.48 117.09,54.23 118.49,54.23 118.75,54.48 118.75,55.5 118.62,55.63 117.09,55.63
VLED- on TOP: 114.55,57.15 114.55,55.75 114.81,55.5 115.32,55.5 115.57,55.75 115.57,56.9 115.82,57.15 116.46,57.15 116.59,57.28 116.59,57.78 116.46,57.91 115.7,57.91 115.32,57.53 114.94,57.53
N17773558 on TOP: 115.95,37.59 117.86,37.59 118.11,37.34 118.11,35.43 117.73,35.05 110.74,35.05 110.36,35.43 110.36,38.86 110.62,39.12 111.38,39.12 112.39,38.1 115.44,38.1
N17773576 on TOP: 105.41,39.12 105.41,35.69 105.92,35.18 108.2,35.18 108.33,35.31 108.33,39.37 108.2,39.5 105.79,39.5
N19875497 on TOP: 115.19,53.21 115.19,50.04 115.44,49.78 117.86,49.78 118.36,50.29 118.36,53.09 117.98,53.47 115.44,53.47
N19897306 on TOP: 32.77,68.07 32.77,66.17 32.38,65.79 32.38,65.15 32.51,65.02 34.67,65.02 34.92,65.28 35.31,65.28 36.32,66.29 36.32,66.67 36.58,66.93 38.1,66.93 38.23,67.06 38.23,67.44 37.97,67.69 36.32,67.69 35.64,67.01 35,67.01 34.7,67.31 34.16,67.31 33.78,67.69 33.78,68.07 33.53,68.33 33.02,68.33
N19978083 on TOP: 11.56,7.62 12.32,8.38 12.32,10.92 10.67,12.57 9.14,12.57 8.89,12.32 8.89,11.56 8.51,11.18 8.51,8 8.89,7.62

Small or netless copper shapes (teardrops, artwork), in the pictures only: 1 on TOP

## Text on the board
Ref Des/Silkscreen Bottom: RTC | SD-CARD | SIM-CARD | D3N | D2N | CKN | D1N | D0N | V+ | V- | D3P | D2P | CKP | D1P | D0P | GND | 3V3 | RST | 1V8
Ref Des/Silkscreen Top: USEL | VCC | LED- | VCCLCD | RTC | D19 | 1V8 | D12 | D11 | D10 | D7 | D6 | D5 | GND | D4 | D3 | HSYNC | CLK | 3V3 | D14 | DE | EMMC | VSYNC | D13 | PS | AUDIO OUT | CSI | LINE IN | ENTER | HOME | I2S | VOL | MENU | HDMI | PWRON | FEL | TPAD | 4G | DC-5V | LCD | DEBUG | GPS | DSI | TS | BAT | LDO3 | VBAT | 5V | SDA | SCK | TWI | IO | PH10 | PH4 | ADC1 | ADC | ADC0 | S-TWI | TX | RX | BT | WIFI | A | 20191225 4L | Lindenis_V536_DIBAN_V2_0
User.11: FIGURE | SIZE | 8.0 | 12.0 | 25.59 | 27.56 | 29.53 | 31.5 | 35.43 | 39.37 | 43.31 | 47.24 | 51.97 | 75.98 | 90.55 | 125.98 | 23.62 | 62.99 | 131.89 | 47.24x19.69 | 66.93x35.43 | 106.3x35.43 | DRILL CHART: TOP to BOTTOM | ALL UNITS ARE IN MILS | PLATED | NON-PLATED | QTY | 1857 | 97 | 2 | 1 | 19 | 28 | 5 | 8 | 51 | 3 | 14 | 10 | 4
